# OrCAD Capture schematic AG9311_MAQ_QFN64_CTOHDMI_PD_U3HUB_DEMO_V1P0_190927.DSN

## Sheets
1 P01 Revision History: title: Revision History; rev: 1.0; note: AG9311-MAQ_QFN64_CtoHDMI_PD_U3HUB
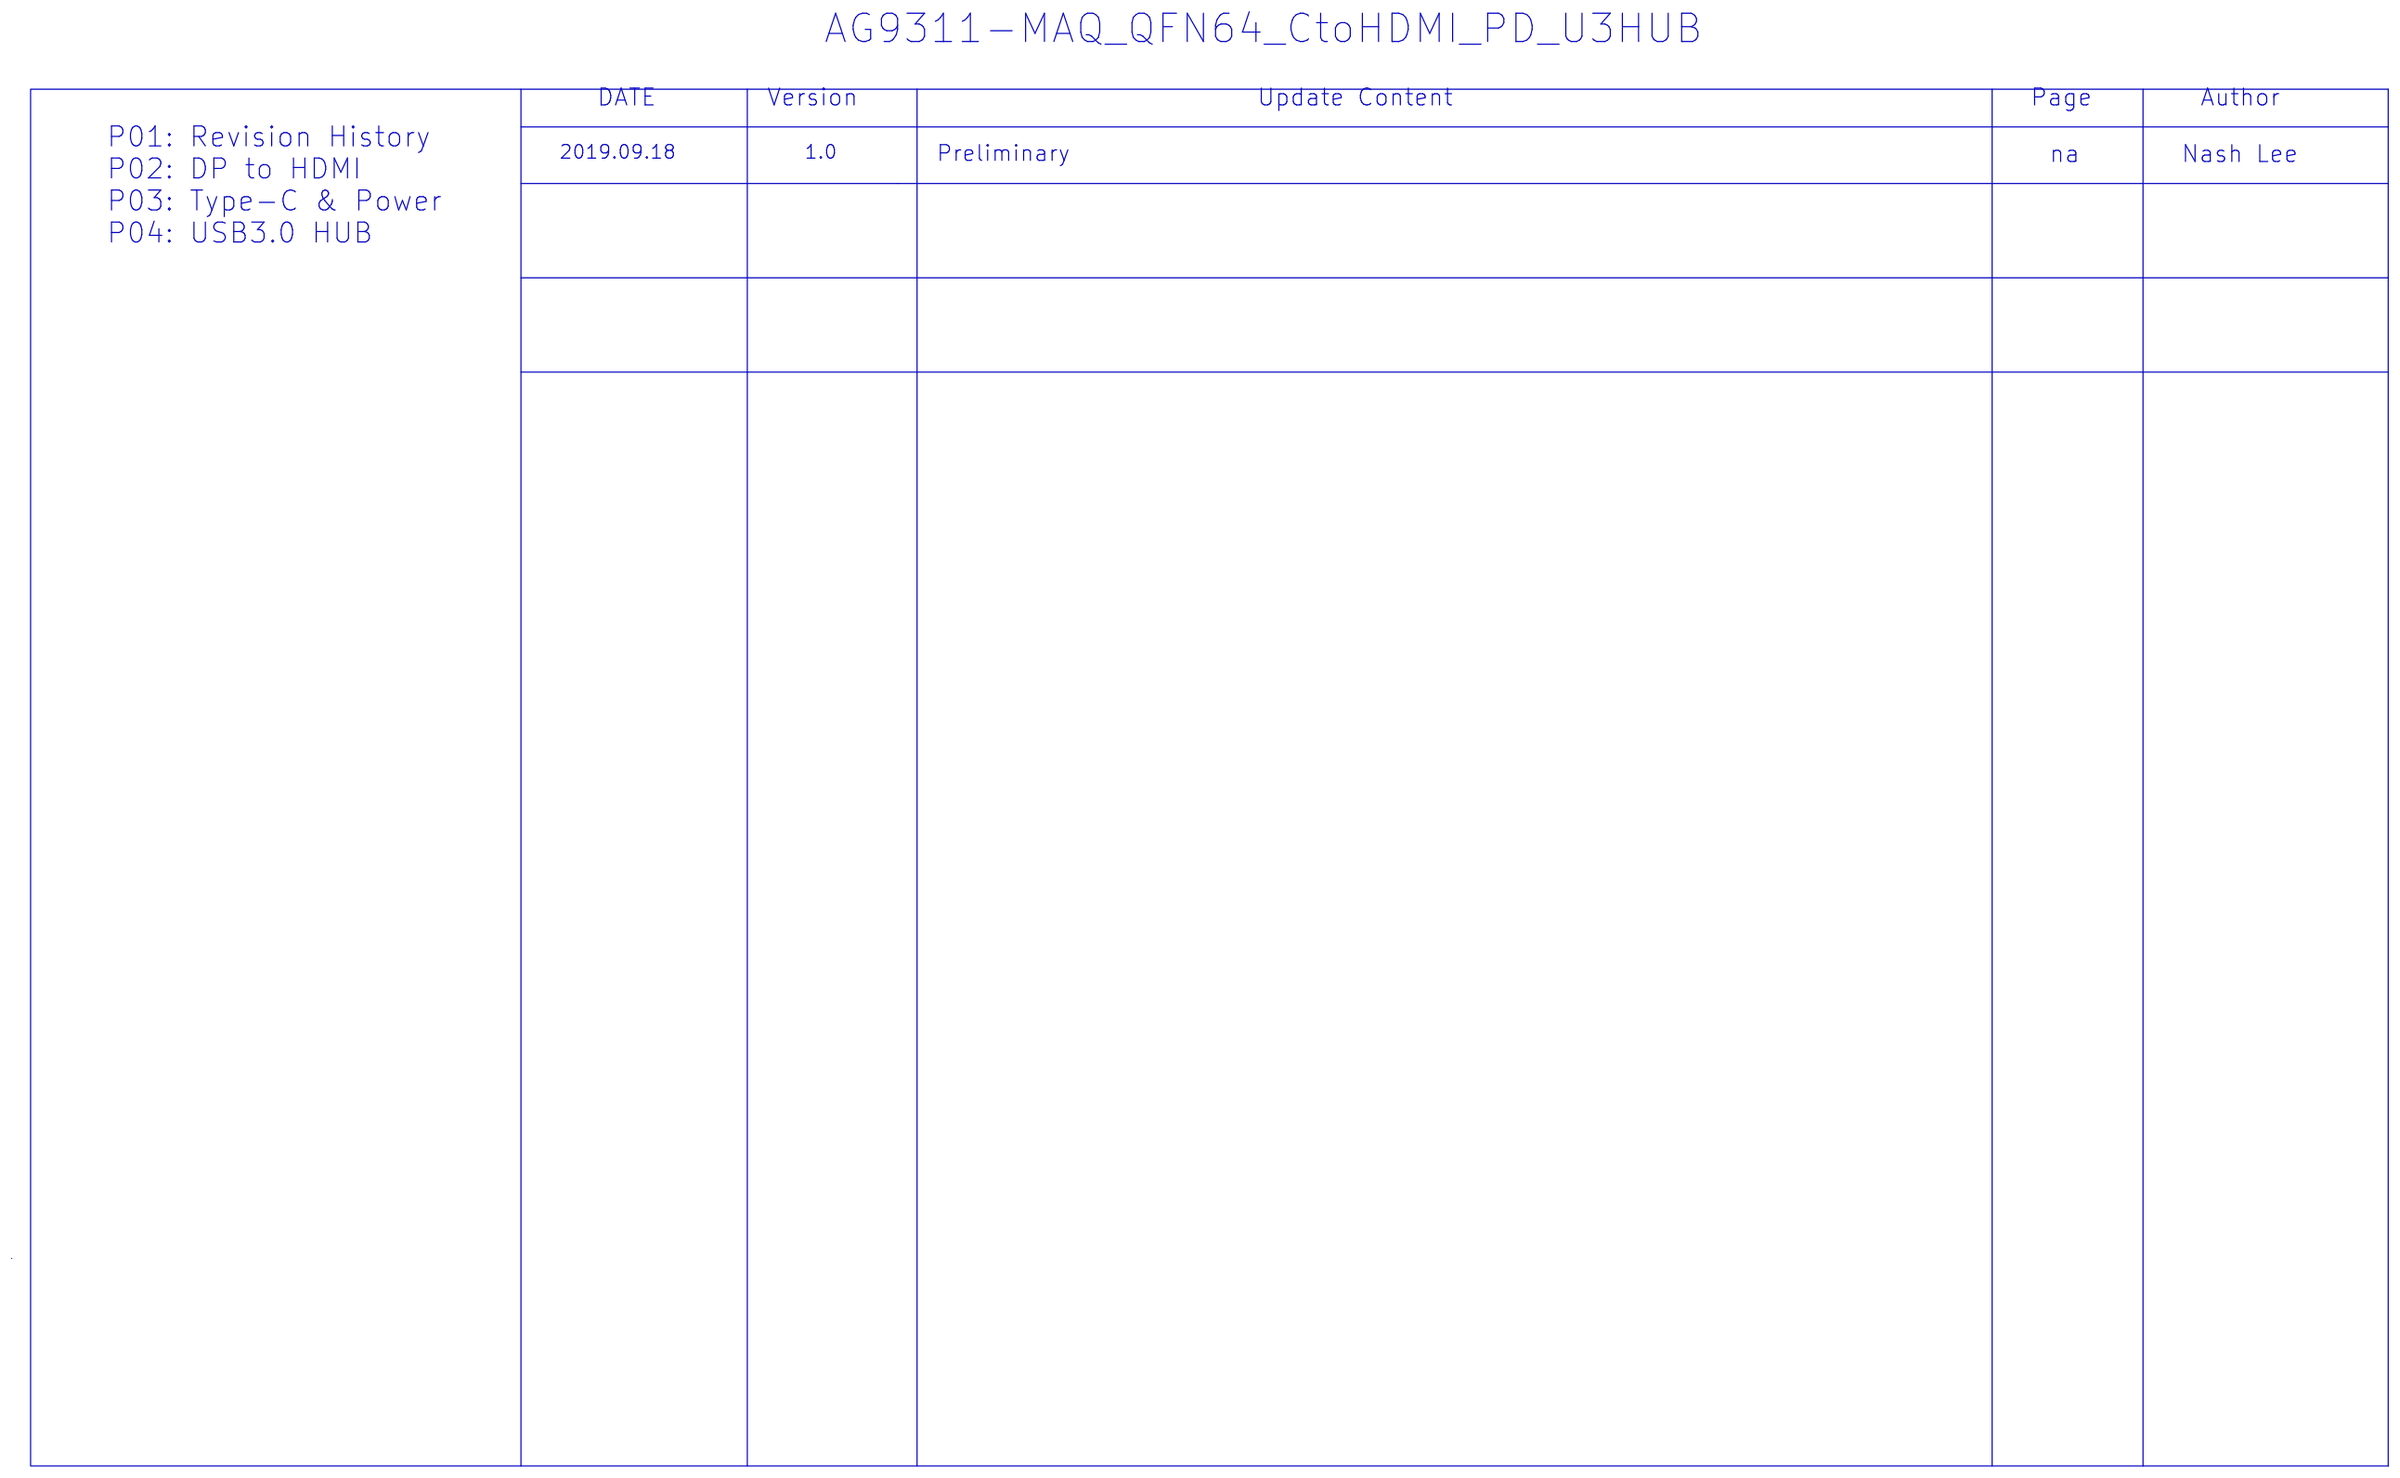
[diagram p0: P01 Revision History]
2 P02 DP to HDMI: size C; title: DP to HDMI
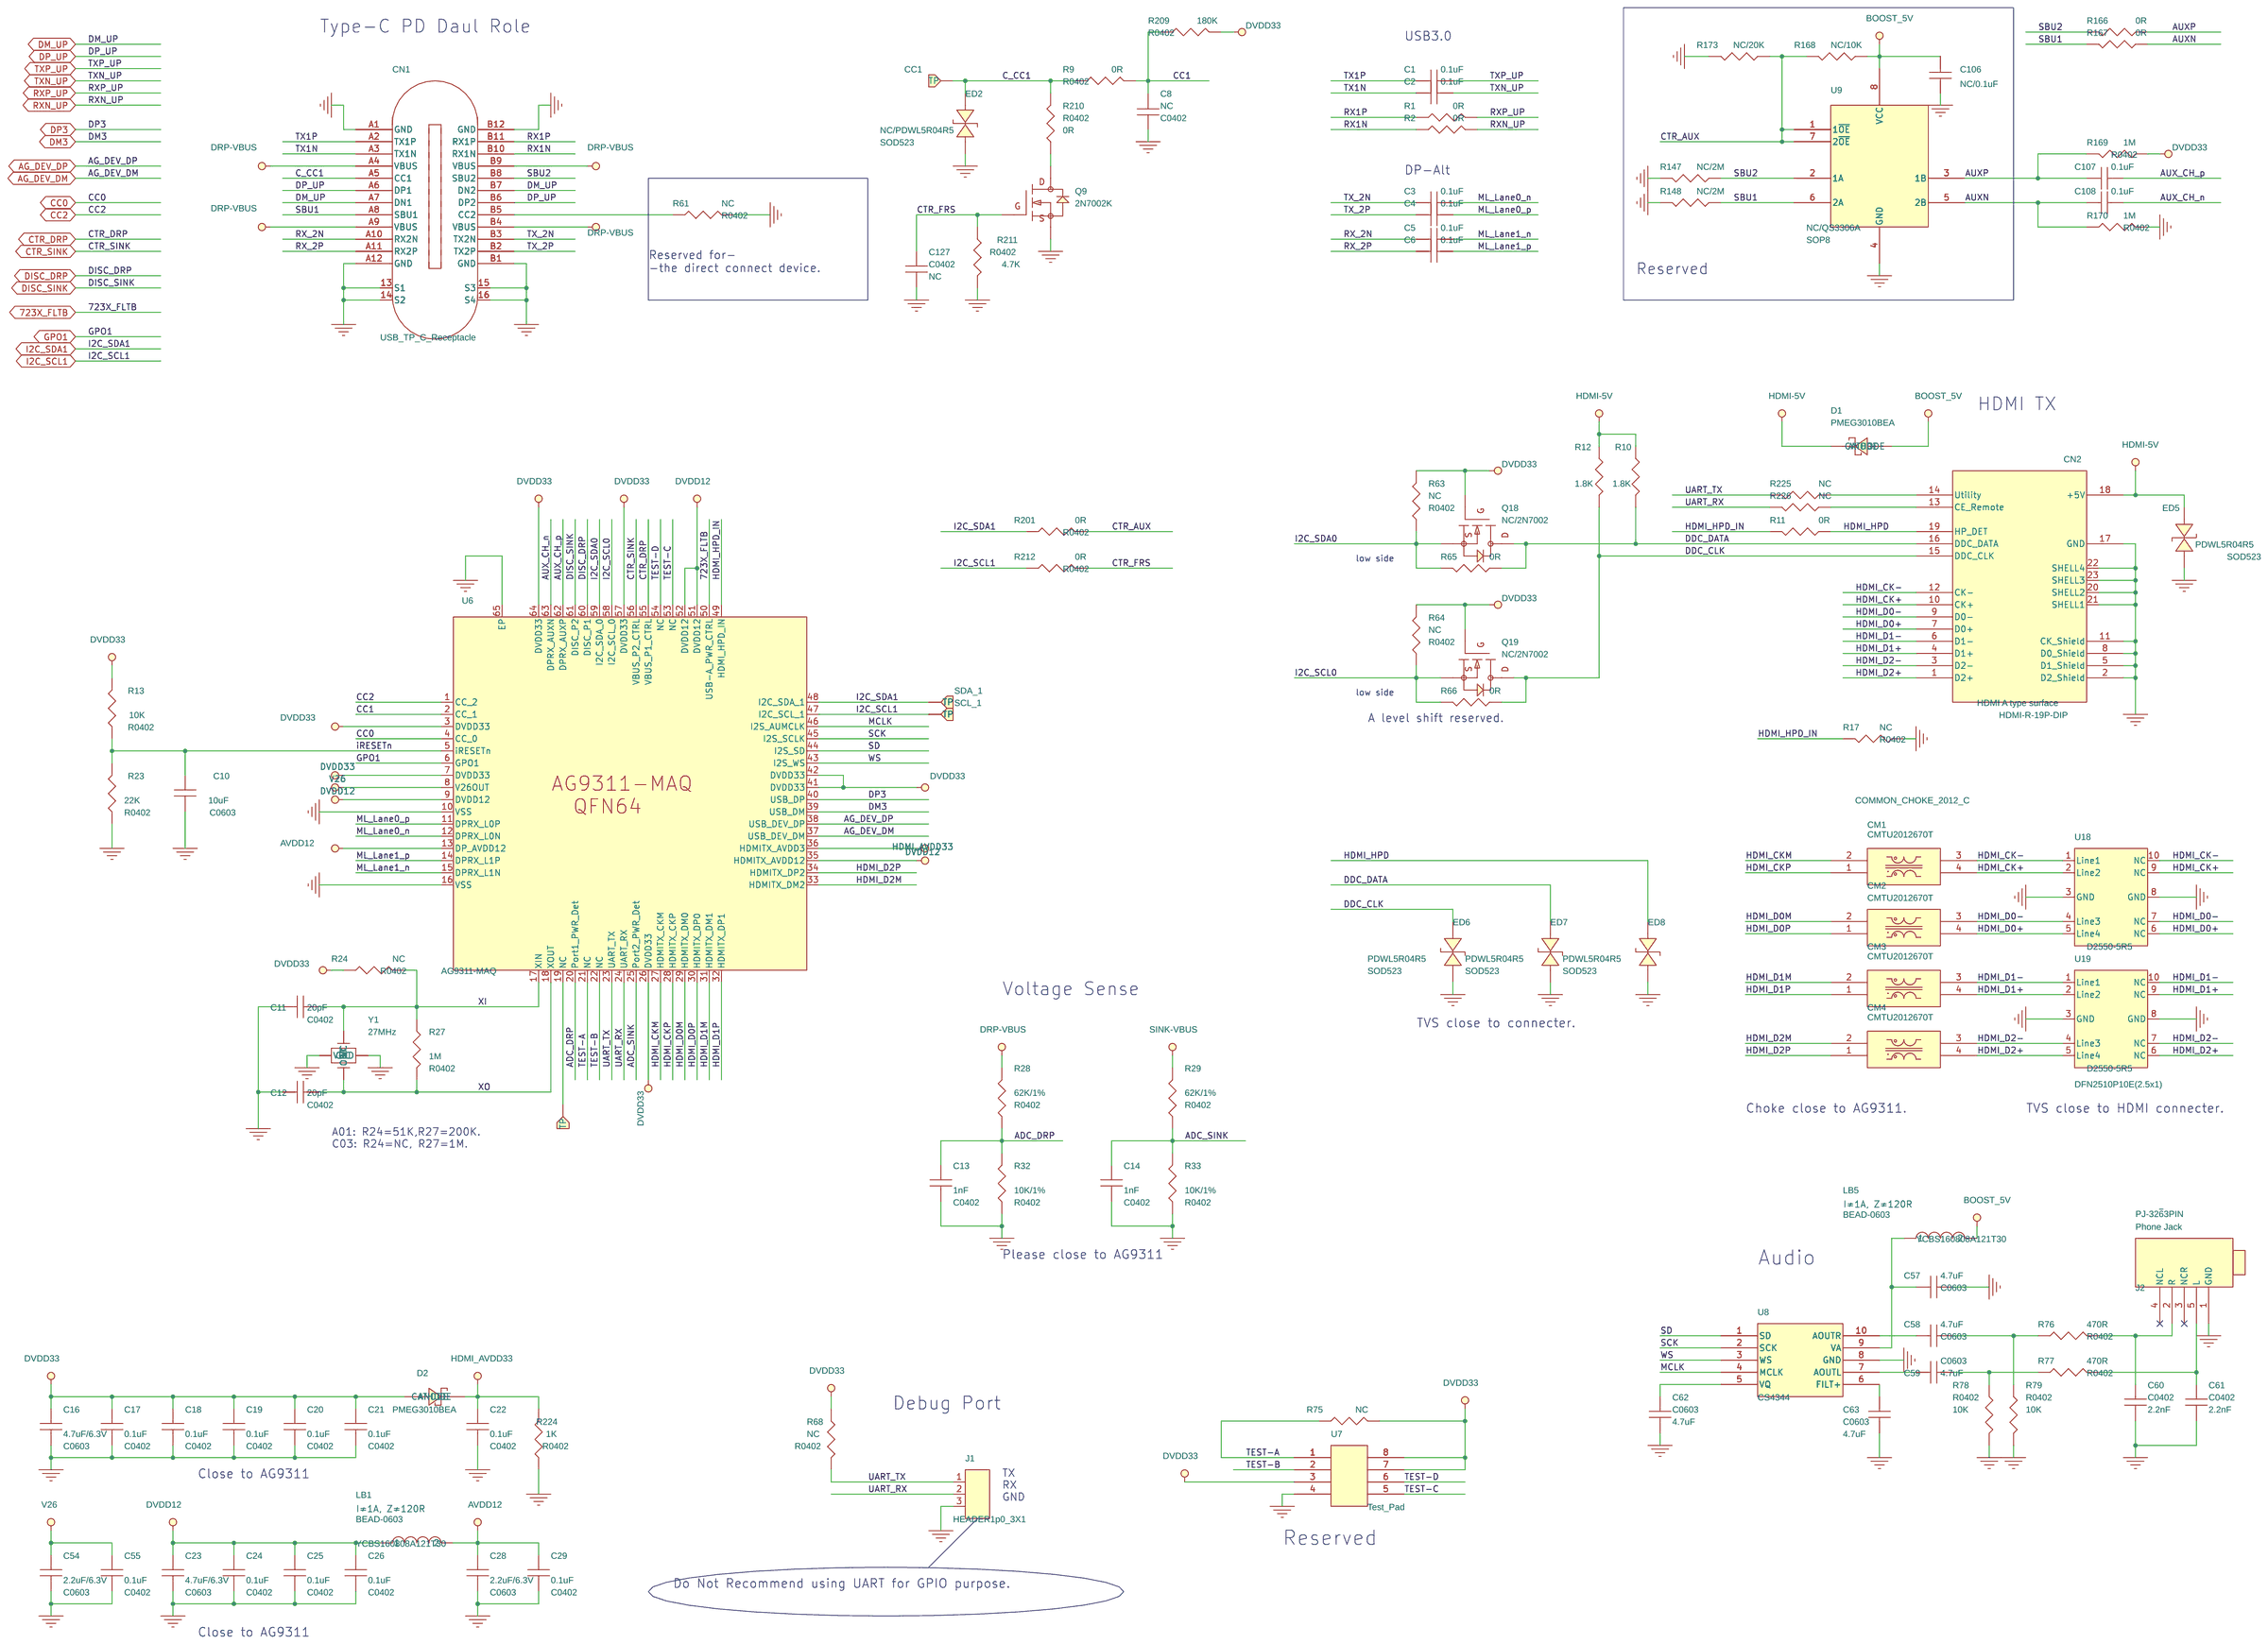
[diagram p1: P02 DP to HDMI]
3 P03 Type-C & Power: size C; title: Type-C & Power
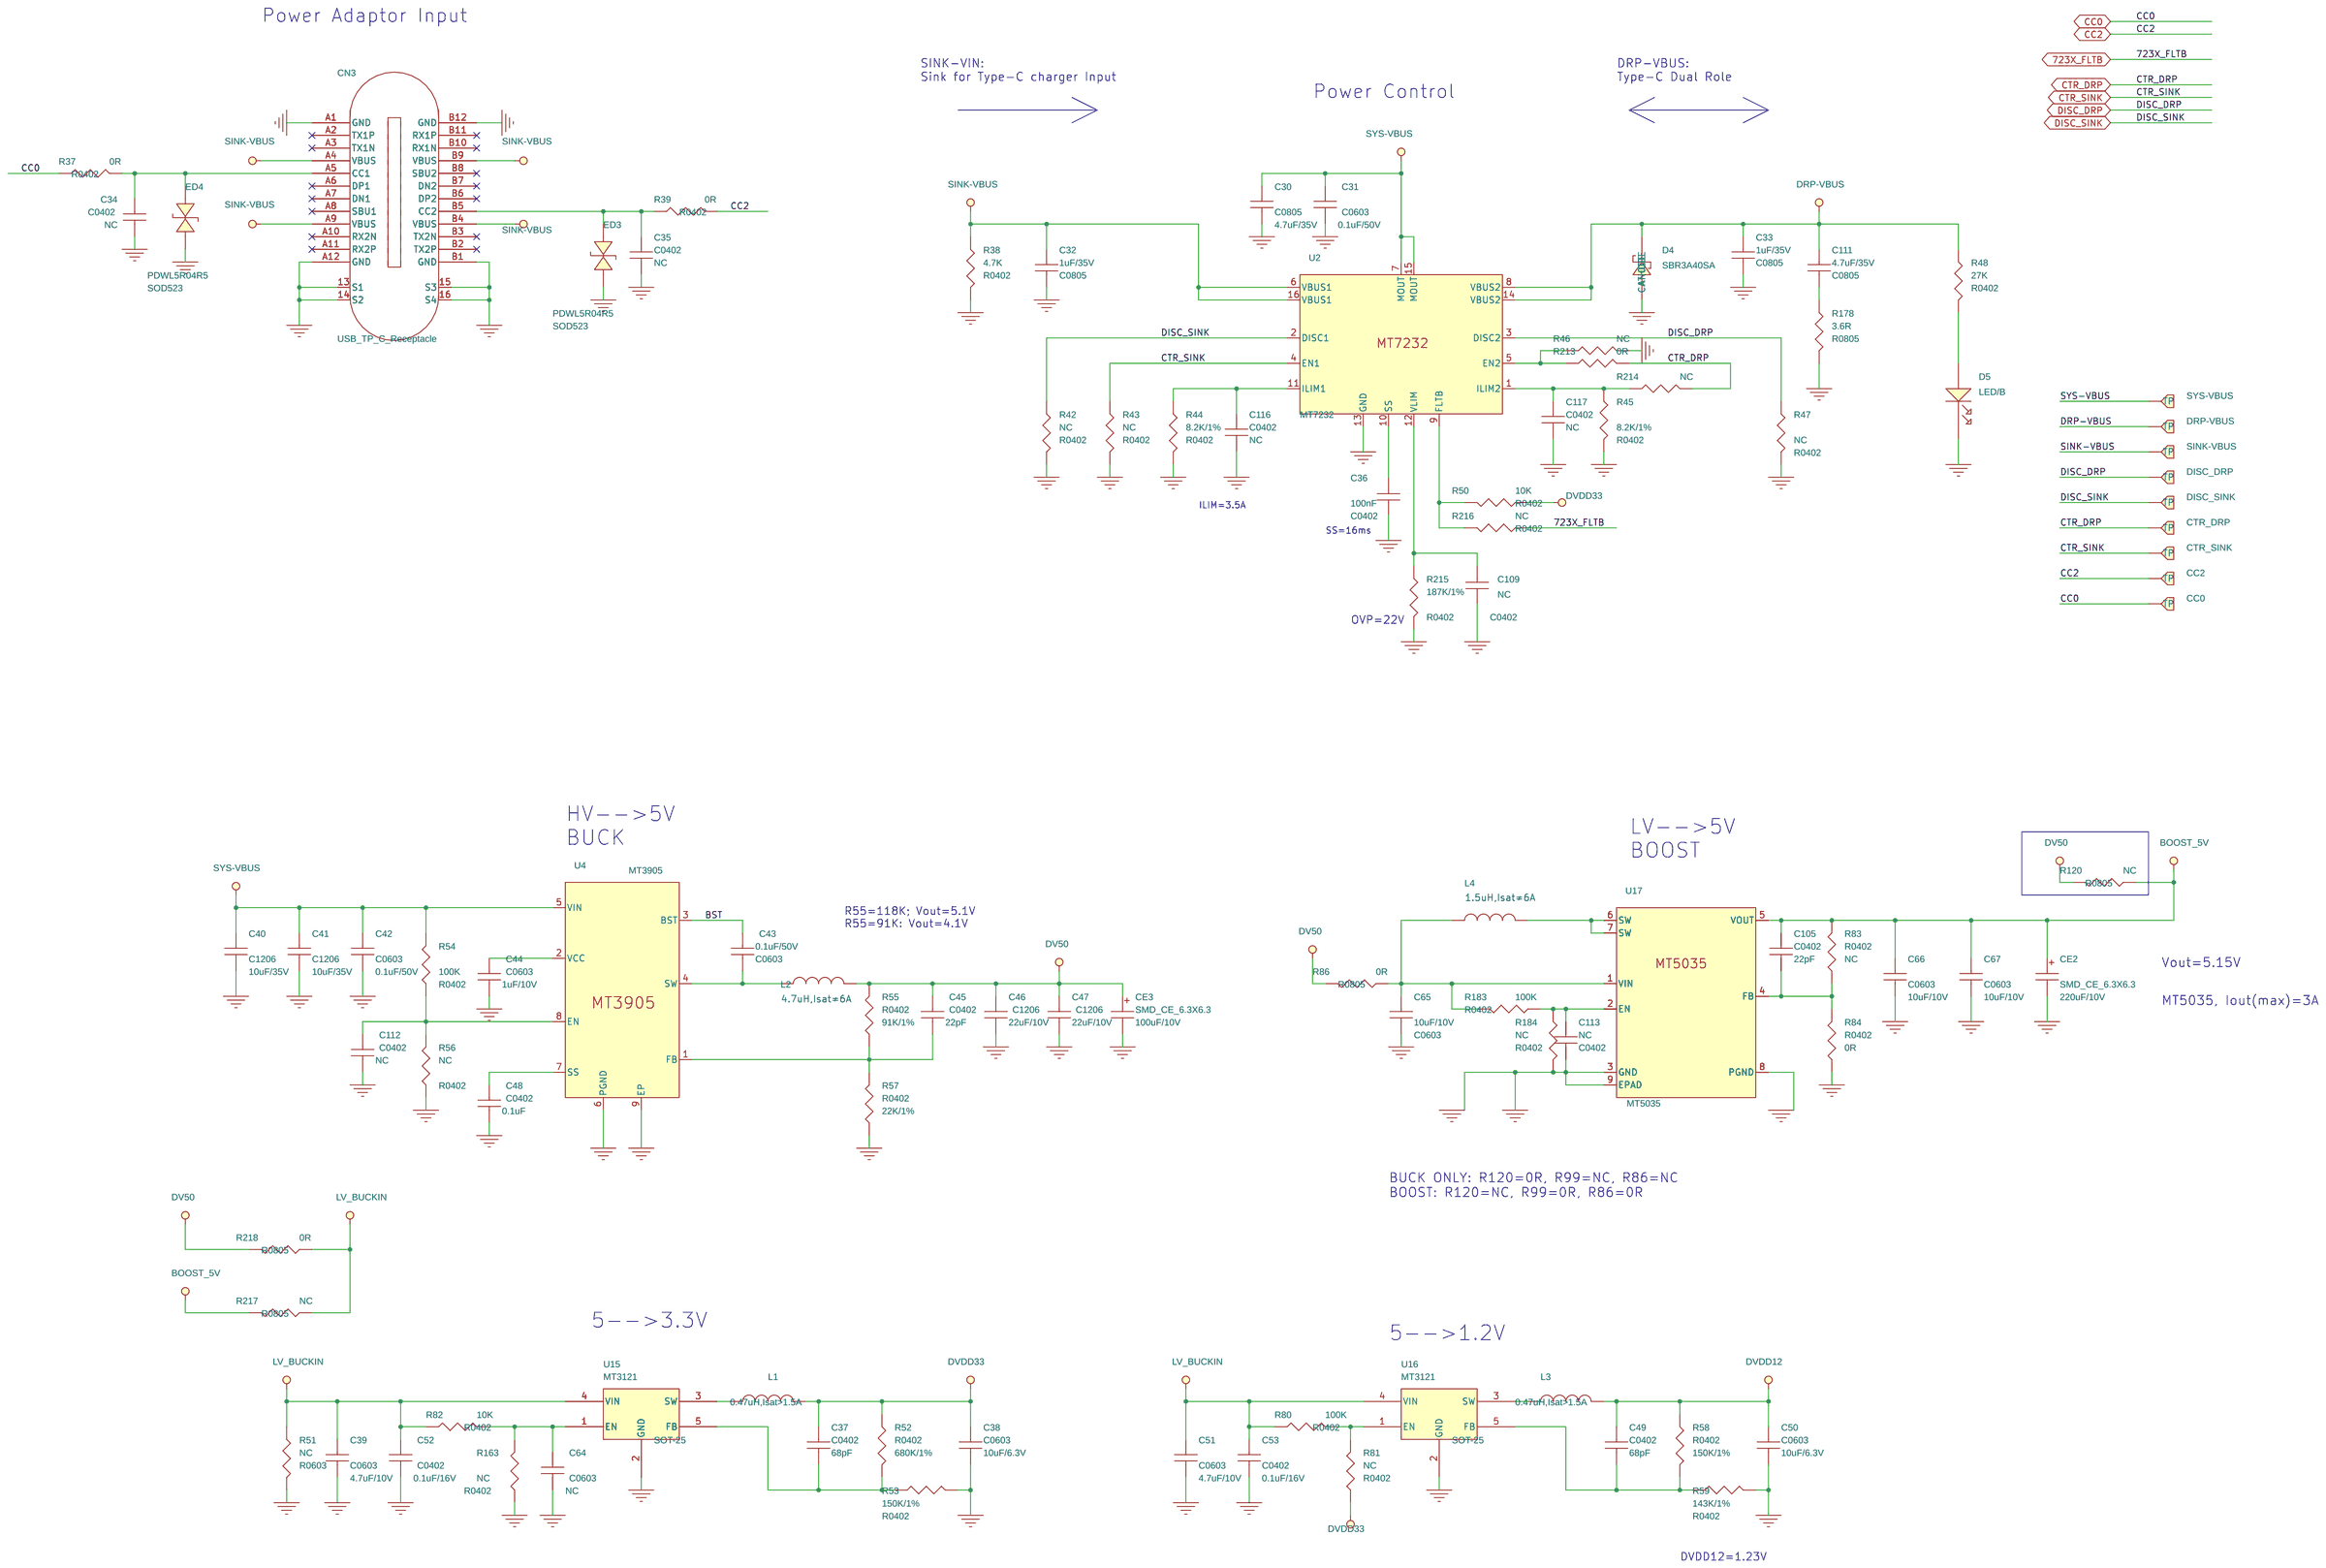
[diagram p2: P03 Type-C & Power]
4 P04 USB3.0 HUB: size C; title: U3HUB
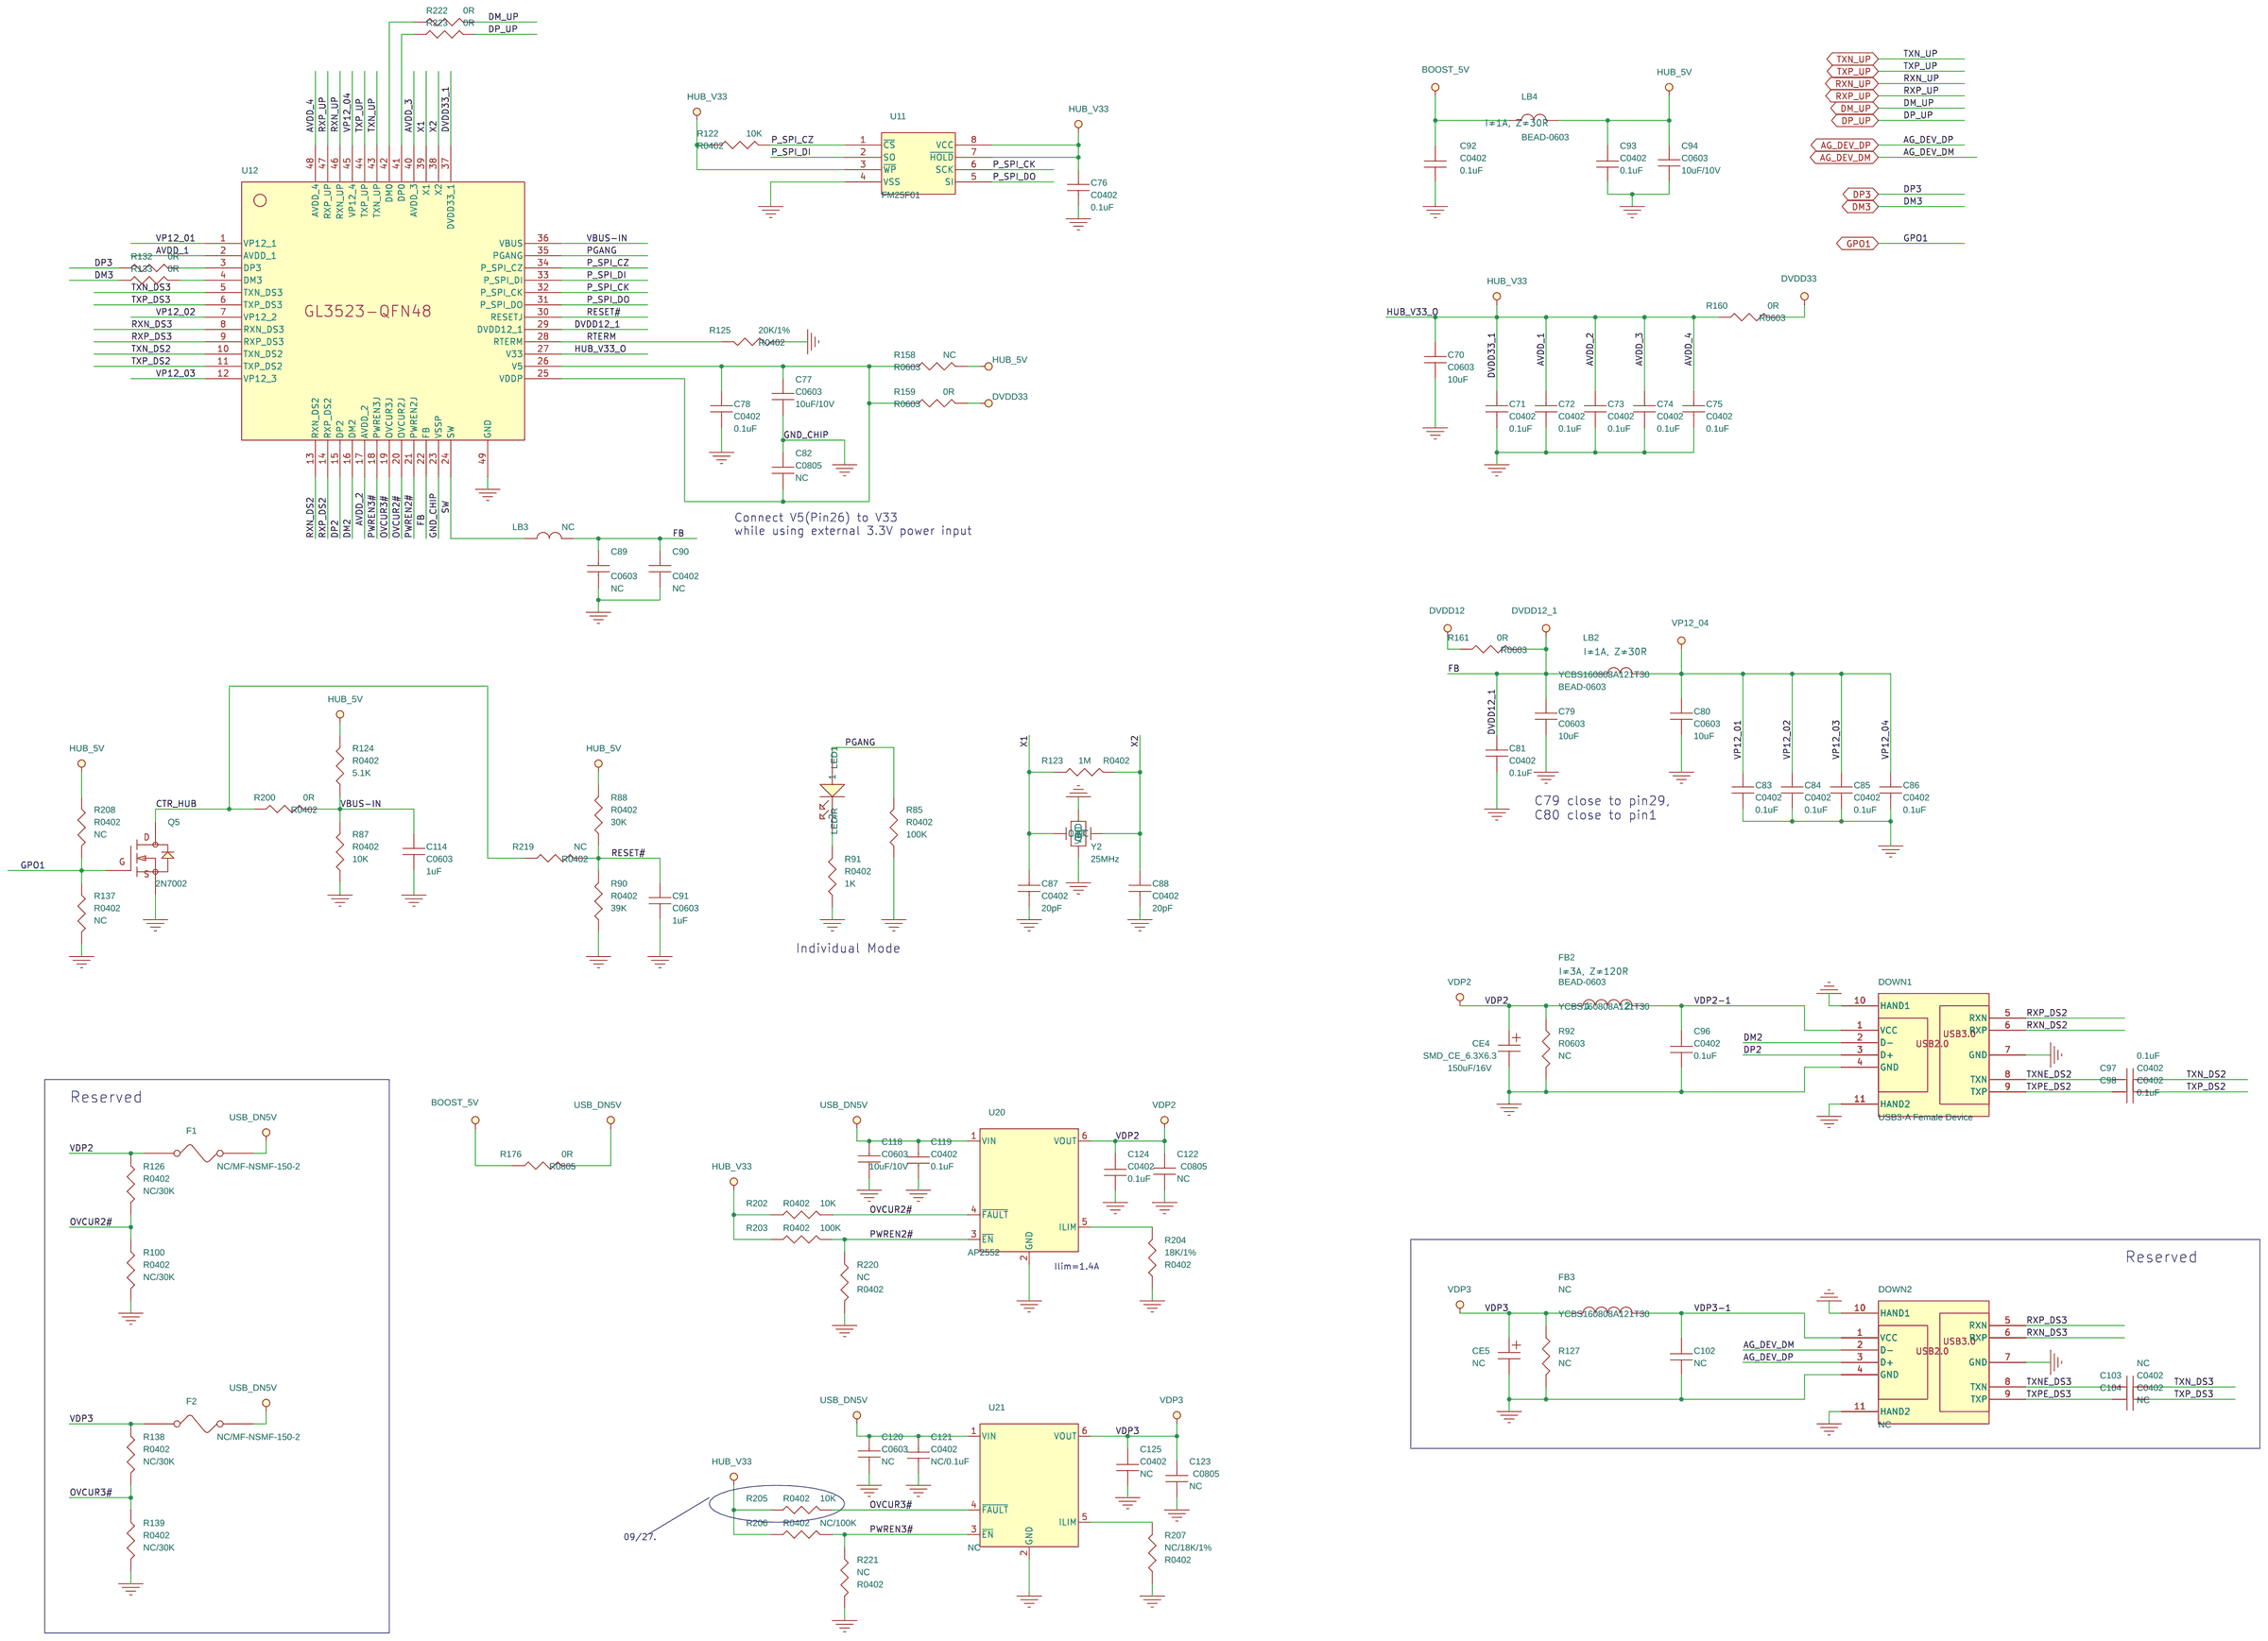
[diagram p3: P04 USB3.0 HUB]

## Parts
sheet P02 DP to HDMI
C1  0.1uF  [C0402]
C2  0.1uF  [C0402]
C3  0.1uF  [C0402]
C4  0.1uF  [C0402]
C5  0.1uF  [C0402]
C6  0.1uF  [C0402]
C8  NC  [C0402]
C10  10uF  [C0603]
C11  20pF  [C0402]
C12  20pF  [C0402]
C13  1nF  [C0402]
C14  1nF  [C0402]
C16  4.7uF/6.3V  [C0603]
C17  0.1uF  [C0402]
C18  0.1uF  [C0402]
C19  0.1uF  [C0402]
C20  0.1uF  [C0402]
C21  0.1uF  [C0402]
C22  0.1uF  [C0402]
C23  4.7uF/6.3V  [C0603]
C24  0.1uF  [C0402]
C25  0.1uF  [C0402]
C26  0.1uF  [C0402]
C28  2.2uF/6.3V  [C0603]
C29  0.1uF  [C0402]
C54  2.2uF/6.3V  [C0603]
C55  0.1uF  [C0402]
C57  4.7uF  [C0603]
C58  4.7uF  [C0603]
C59  4.7uF  [C0603]
C60  2.2nF  [C0402]
C61  2.2nF  [C0402]
C62  4.7uF  [C0603]
C63  4.7uF  [C0603]
C106  NC/0.1uF  [C0402]
C107  0.1uF  [C0402]
C108  0.1uF  [C0402]
C127  NC  [C0402]
CM1  CMTU2012670T  [COMMON_CHOKE_2012_C]
CM2  CMTU2012670T  [COMMON_CHOKE_2012_C]
CM3  CMTU2012670T  [COMMON_CHOKE_2012_C]
CM4  CMTU2012670T  [COMMON_CHOKE_2012_C]
CN1  USB_TP_C_Receptacle  [USB_TYPE_C_FEMALE_DIP_A0353-001]
CN2  HDMI A type surface  [HDMI-R-19P-DIP]
D1  PMEG3010BEA  [SOD323]
D2  PMEG3010BEA  [SOD323]
ED2  NC/PDWL5R04R5  [SOD523]
ED5  PDWL5R04R5  [SOD523]
ED6  PDWL5R04R5  [SOD523]
ED7  PDWL5R04R5  [SOD523]
ED8  PDWL5R04R5  [SOD523]
J1  HEADER1p0_3X1  [HEADER1p0_3X1]
J2  Phone Jack  [PJ-326\3PIN]
LB1  I≠1A, Z≠120R  [BEAD-0603]
LB5  I≠1A, Z≠120R  [BEAD-0603]
Q9  2N7002K  [SOT23-GDS]
Q18  NC/2N7002  [SOT23-GDS]
Q19  NC/2N7002  [SOT23-GDS]
R1  0R  [R0402]
R2  0R  [R0402]
R9  0R  [R0402]
R10  1.8K  [R0402]
R11  0R  [R0402]
R12  1.8K  [R0402]
R13  10K  [R0402]
R17  NC  [R0402]
R23  22K  [R0402]
R24  NC  [R0402]
R27  1M  [R0402]
R28  62K/1%  [R0402]
R29  62K/1%  [R0402]
R32  10K/1%  [R0402]
R33  10K/1%  [R0402]
R61  NC  [R0402]
R63  NC  [R0402]
R64  NC  [R0402]
R65  0R  [R0402]
R66  0R  [R0402]
R68  NC  [R0402]
R75  NC  [R0402]
R76  470R  [R0402]
R77  470R  [R0402]
R78  10K  [R0402]
R79  10K  [R0402]
R147  NC/2M  [R0402]
R148  NC/2M  [R0402]
R166  0R  [R0402]
R167  0R  [R0402]
R168  NC/10K  [R0402]
R169  1M  [R0402]
R170  1M  [R0402]
R173  NC/20K  [R0402]
R201  0R  [R0402]
R209  180K  [R0402]
R210  0R  [R0402]
R211  4.7K  [R0402]
R212  0R  [R0402]
R224  1K  [R0402]
R225  NC  [R0402]
R226  NC  [R0402]
TP1  CC1  [TEST-PAD]
TP12  SYS-VBUS  [TEST-PAD]
TP13  SDA_1  [TEST-PAD]
TP14  SCL_1  [TEST-PAD]
U6  AG9311-MAQ  [QFN64P(8X8)-0.4-EP]
U7  Test_Pad  [SOP8]
U8  CS4344  [TSSOP10]
U9  NC/QS3306A  [SOP8]
U18  D2550-5R5  [DFN2510P10E(2.5x1)]
U19  D2550-5R5  [DFN2510P10E(2.5x1)]
Y1  27MHz  [XTAL3225]
sheet P03 Type-C & Power
C30  4.7uF/35V  [C0805]
C31  0.1uF/50V  [C0603]
C32  1uF/35V  [C0805]
C33  1uF/35V  [C0805]
C34  NC  [C0402]
C35  NC  [C0402]
C36  100nF  [C0402]
C37  68pF  [C0402]
C38  10uF/6.3V  [C0603]
C39  4.7uF/10V  [C0603]
C40  10uF/35V  [C1206]
C41  10uF/35V  [C1206]
C42  0.1uF/50V  [C0603]
C43  0.1uF/50V  [C0603]
C44  1uF/10V  [C0603]
C45  22pF  [C0402]
C46  22uF/10V  [C1206]
C47  22uF/10V  [C1206]
C48  0.1uF  [C0402]
C49  68pF  [C0402]
C50  10uF/6.3V  [C0603]
C51  4.7uF/10V  [C0603]
C52  0.1uF/16V  [C0402]
C53  0.1uF/16V  [C0402]
C64  NC  [C0603]
C65  10uF/10V  [C0603]
C66  10uF/10V  [C0603]
C67  10uF/10V  [C0603]
C105  22pF  [C0402]
C109  NC  [C0402]
C111  4.7uF/35V  [C0805]
C112  NC  [C0402]
C113  NC  [C0402]
C116  NC  [C0402]
C117  NC  [C0402]
CE2  220uF/10V  [SMD_CE_6.3X6.3]
CE3  100uF/10V  [SMD_CE_6.3X6.3]
CN3  USB_TP_C_Receptacle  [USB_TYPE_C_FEMALE_DIP_A0353-001]
D4  SBR3A40SA  [SMA-SBR3A40SA]
D5  LED/B  [LED0603]
ED3  PDWL5R04R5  [SOD523]
ED4  PDWL5R04R5  [SOD523]
L1  0.47uH,Isat>1.5A  [GSDR31]
L2  4.7uH,Isat≠6A  [SMD-L-STMPD0603]
L3  0.47uH,Isat>1.5A  [GSDR31]
L4  1.5uH,Isat≠6A  [SMD-L-STMPD0603]
R37  0R  [R0402]
R38  4.7K  [R0402]
R39  0R  [R0402]
R42  NC  [R0402]
R43  NC  [R0402]
R44  8.2K/1%  [R0402]
R45  8.2K/1%  [R0402]
R46  NC  [R0402]
R47  NC  [R0402]
R48  27K  [R0402]
R50  10K  [R0402]
R51  NC  [R0603]
R52  680K/1%  [R0402]
R53  150K/1%  [R0402]
R54  100K  [R0402]
R55  91K/1%  [R0402]
R56  NC  [R0402]
R57  22K/1%  [R0402]
R58  150K/1%  [R0402]
R59  143K/1%  [R0402]
R80  100K  [R0402]
R81  NC  [R0402]
R82  10K  [R0402]
R83  NC  [R0402]
R84  0R  [R0402]
R86  0R  [R0805]
R120  NC  [R0805]
R163  NC  [R0402]
R178  3.6R  [R0805]
R183  100K  [R0402]
R184  NC  [R0402]
R213  0R  [R0402]
R214  NC  [R0402]
R215  187K/1%  [R0402]
R216  NC  [R0402]
R217  NC  [R0805]
R218  0R  [R0805]
TP3  SYS-VBUS  [TEST-PAD]
TP4  DRP-VBUS  [TEST-PAD]
TP5  SINK-VBUS  [TEST-PAD]
TP6  DISC_DRP  [TEST-PAD]
TP7  DISC_SINK  [TEST-PAD]
TP8  CTR_DRP  [TEST-PAD]
TP9  CTR_SINK  [TEST-PAD]
TP10  CC2  [TEST-PAD]
TP11  CC0  [TEST-PAD]
U2  MT7232  [QFN16P(2.3X3.5)]
U4  MT3905  [SOP8-EP]
U15  MT3121  [SOT-25]
U16  MT3121  [SOT-25]
U17  MT5035  [SOP8-EP]
sheet P04 USB3.0 HUB
C70  10uF  [C0603]
C71  0.1uF  [C0402]
C72  0.1uF  [C0402]
C73  0.1uF  [C0402]
C74  0.1uF  [C0402]
C75  0.1uF  [C0402]
C76  0.1uF  [C0402]
C77  10uF/10V  [C0603]
C78  0.1uF  [C0402]
C79  10uF  [C0603]
C80  10uF  [C0603]
C81  0.1uF  [C0402]
C82  NC  [C0805]
C83  0.1uF  [C0402]
C84  0.1uF  [C0402]
C85  0.1uF  [C0402]
C86  0.1uF  [C0402]
C87  20pF  [C0402]
C88  20pF  [C0402]
C89  NC  [C0603]
C90  NC  [C0402]
C91  1uF  [C0603]
C92  0.1uF  [C0402]
C93  0.1uF  [C0402]
C94  10uF/10V  [C0603]
C96  0.1uF  [C0402]
C97  0.1uF  [C0402]
C98  0.1uF  [C0402]
C102  NC  [C0402]
C103  NC  [C0402]
C104  NC  [C0402]
C114  1uF  [C0603]
C118  10uF/10V  [C0603]
C119  0.1uF  [C0402]
C120  NC  [C0603]
C121  NC/0.1uF  [C0402]
C122  NC  [C0805]
C123  NC  [C0805]
C124  0.1uF  [C0402]
C125  NC  [C0402]
CE4  150uF/16V  [SMD_CE_6.3X6.3]
CE5  NC  [SMD_CE_6.3X6.3]
DOWN1  USB3-A Female Device  [USB3.0-AF-CONN]
DOWN2  NC  [USB3.0-AF-CONN]
F1  NC/MF-NSMF-150-2  [FUSE1206]
F2  NC/MF-NSMF-150-2  [FUSE1206]
FB2  I≠3A, Z≠120R  [BEAD-0603]
FB3  NC  [BEAD-0603]
LB2  I≠1A, Z≠30R  [BEAD-0603]
LB3  NC  [GSDR31]
LB4  I≠1A, Z≠30R  [BEAD-0603]
LED1  LED/R  [LED0603]
Q5  2N7002  [SOT23-GDS]
R85  100K  [R0402]
R87  10K  [R0402]
R88  30K  [R0402]
R90  39K  [R0402]
R91  1K  [R0402]
R92  NC  [R0603]
R100  NC/30K  [R0402]
R122  10K  [R0402]
R123  1M  [R0402]
R124  5.1K  [R0402]
R125  20K/1%  [R0402]
R126  NC/30K  [R0402]
R127  NC  [R0603]
R132  0R  [R0402]
R133  0R  [R0402]
R137  NC  [R0402]
R138  NC/30K  [R0402]
R139  NC/30K  [R0402]
R158  NC  [R0603]
R159  0R  [R0603]
R160  0R  [R0603]
R161  0R  [R0603]
R176  0R  [R0805]
R200  0R  [R0402]
R202  10K  [R0402]
R203  100K  [R0402]
R204  18K/1%  [R0402]
R205  10K  [R0402]
R206  NC/100K  [R0402]
R207  NC/18K/1%  [R0402]
R208  NC  [R0402]
R219  NC  [R0402]
R220  NC  [R0402]
R221  NC  [R0402]
R222  0R  [R0402]
R223  0R  [R0402]
U11  FM25F01  [SOP8]
U12  GL3523_QFN48_V094-1_42  [QFN48P(6X6)-0.4-EP]
U20  AP2552  [SOT-26]
U21  NC  [SOT-26]
Y2  25MHz  [XTAL3225]

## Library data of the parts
C1-C6 C8 = CAP_NP_1
C10-C14 C16 C23 C28 C37-C39 C49-C51 C54 C65-C67 C105 = CAP_0603_5
C17-C22 C24-C26 C29 C55 C92 C93 C96-C98 C102-C104 C107 C108 C119 C121 C124 C125 = CAP_0402_1
C57-C63 = CAP_0603_8
C106 = CAP_0402_0
C127 = CAP_NP_0
CM1-CM4 = CM_TCF03025DH
CN1 CN3 = USB_TP_C_Receptacle
CN2 = HDMI_CNNT_5: P/N: 11.190M4G007; PN0: 11.190M4G002; PN0D: CNNT HDMI M 19P 0.5mm SMT/RT 47151-1101; "MOLEX
D1 = DIODE_SCHOTTKY_2: Location: T; P/N: 09.PMEG4G001
D2 = DIODE_SCHOTTKY_3: Location: T; P/N: 09.PMEG4G001
ED2-ED8 = ESD_0: Layer: BOT; P/N: 09.PESD5GV0B
J1 = HEADER254_3X1
J2 = 74AUP1T45_1
FB2 LB1 = INDUCTOR: P/N: YCBS160808A121T30
LB5 = INDUCTOR_1: P/N: YCBS160808A121T30
Q9 = AO3418
Q5 Q18 Q19 = 2N7002_0
R1 R2 = R-0402
R9 R209-R211 = R_0
R10-R13 R17 R23 R24 R27-R29 R32 R33 R38 R42 R43 R45-R48 R52 R53 R58 R59 R65 R66 R68 R76-R79 R147 R148 R166-R170 R173 R178 R200 R201 R212-R214 R219 R224-R226 = R-0603_12
R61 = R-0603_9
R54-R57 R63 R64 R83 R84 R86 R120 R183 R184 R217 R218 = R-0603_7
R51 R75 R80-R82 R163 = R_6
TP1 TP3-TP14 = T_POINT_F
U6 = AG9311-MAQ-QFN64_2
U7 = FM25F005_SOP8_1
U8 = 100201_SO_5
U9 = 24C16_7: Layer: TOP; P/N: PCA9306DCUR
U18 U19 = AZ1023-04F
Y1 Y2 = CRYSTAL_SMD
C30 C32 C33 C40 C41 C46 C47 C111 C122 C123 = CAP_1206
C31 C34 C35 C42-C45 C48 C52 C53 C64 C70-C76 C78-C81 C83-C91 C94 C112-C114 C116-C118 C120 = CAP_0603
C36 C109 = CAP_0805_0
CE2 CE3 = ECAP_D_0
D4 = DIODE_SCHOTTKY_5: Location: T; P/N: 09.PMEG4G001
D5 = LED_5
L1 L3 = INDUCTOR_5
L2 L4 = INDUCTOR_6
R37 R39 R44 R50 R215 R216 = R-0603_14
U2 = MT7232
U4 = MT3905
U15 U16 = MIC29302_0
U17 = MT5033_0
C77 C82 = CAP_0805
CE4 CE5 = CAP_SMD
DOWN1 DOWN2 = USB3-A_0
F1 F2 = FS-A
FB3 = FB1608: P/N: YCBS160808A121T30
LB2 = GBD201209PGH501N: P/N: YCBS160808A121T30
LB3 = FB-0805
LB4 = GBD201209PGH501N
LED1 = LED-0805_2
R85 R87 R88 R90-R92 R100 R122-R127 R132 R133 R138 R139 R158-R161 R176 R202-R207 R220-R223 = R-0603
R137 R208 = R_7
U11 = CAT25C128_256
U12 = GL3523_QFN48_V094-1_0
U20 U21 = AP2552

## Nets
AVDD12: C28.1 C29.1 LB1.2 U6.13(DP_AVDD12)
DV50: C45.1 C46.1 C47.1 CE3.1 L2.2 R55.2 R86.2 R120.2 R218.2
DVDD12: C23.1 C24.1 C25.1 C26.1 C49.1 C50.1 L3.2 LB1.1 R58.1 R161.2 U6.9(DVDD12) U6.35(HDMITX_AVDD12) U6.51(DVDD12) U6.52(DVDD12)
DVDD33: C16.1 C17.1 C18.1 C19.1 C20.1 C21.1 C37.1 C38.1 D2.A(ANODE) L1.2 Q18.G(GATE) Q19.G(GATE) R13.1 R24.1 R50.2 R52.1 R63.1 R64.1 R68.2 R75.1 R81.1 R159.2 R160.1 R169.1 R209.2 U6.3(DVDD33) U6.7(DVDD33) U6.26(DVDD33) U6.41(DVDD33) U6.42(DVDD33) U6.57(DVDD33) U6.64(DVDD33) U7.3 U7.7 U7.8
GND: C8.1 C10.2 C11.1 C12.1 C13.2 C14.2 C16.2 C17.2 C18.2 C19.2 C20.2 C21.2 C22.2 C23.2 C24.2 C25.2 C26.2 C28.2 C29.2 C30.2 C31.2 C32.2 C33.2 C34.2 C35.2 C36.1 C38.2 C39.2 C40.2 C41.2 C42.2 C44.2 C46.2 C47.2 C48.2 C50.2 C51.2 C52.2 C53.2 C54.2 C55.2 C57.2 C60.2 C61.2 C62.2 C63.2 C64.2 C65.2 C66.2 C67.2 C70.2 C71.2 C72.2 C73.2 C74.2 C75.2 C76.2 C77.2 C78.2 C79.2 C80.2 C81.2 C82.1 C83.2 C84.2 C85.2 C86.2 C87.2 C88.2 C89.2 C90.2 C91.2 C92.1 C93.1 C94.2 C96.1 C102.1 C106.1 C109.1 C112.2 C113.2 C114.2 C116.2 C117.2 C118.2 C119.1 C120.2 C121.1 C122.2 C123.2 C124.1 C125.1 C127.2 CE2.2 CE3.2 CE4.2 CE5.2 CN1.13(S1) CN1.14(S2) CN1.15(S3) CN1.16(S4) CN1.A1(GND) CN1.A12(GND) CN1.B1(GND) CN1.B12(GND) CN2.2(D2_Shield) CN2.5(D1_Shield) CN2.8(D0_Shield) CN2.11(CK_Shield) CN2.17(GND) CN2.20(SHELL2) CN2.21(SHELL1) CN2.22(SHELL4) CN2.23(SHELL3) CN3.13(S1) CN3.14(S2) CN3.15(S3) CN3.16(S4) CN3.A1(GND) CN3.A12(GND) CN3.B1(GND) CN3.B12(GND) D4.A(ANODE) D5.K(CATHODE) DOWN1.4(GND) DOWN1.7(GND) DOWN1.10(HAND1) DOWN1.11(HAND2) DOWN2.4(GND) DOWN2.7(GND) DOWN2.10(HAND1) DOWN2.11(HAND2) ED2.2 ED3.2 ED4.2 ED5.2 ED6.2 ED7.2 ED8.2 J1.3 J2.1(GND) Q5.S(SOURCE) Q9.S(SOURCE) R17.1 R23.2 R32.1 R33.1 R38.2 R42.2 R43.2 R44.2 R45.2 R46.2 R47.2 R51.2 R53.2 R56.1 R57.1 R59.2 R61.2 R78.2 R79.2 R84.1 R85.1 R87.1 R90.1 R91.1 R92.2 R100.2 R125.1 R127.2 R137.2 R139.2 R147.2 R148.2 R163.1 R170.2 R173.1 R178.2 R184.2 R204.1 R207.1 R211.2 R215.1 R220.2 R221.2 R224.1 U2.13(GND) U4.6(PGND) U4.9(EP) U6.10(VSS) U6.16(VSS) U6.65(EP) U7.4 U8.8(GND) U9.4(GND) U11.4(VSS) U12.23(VSSP) U12.49(GND) U15.2(GND) U16.2(GND) U17.3(GND) U17.8(PGND) U17.9(EPAD) U18.3(GND) U18.8(GND) U19.3(GND) U19.8(GND) U20.2(GND) U21.2(GND) Y1.2(GND) Y1.4(VDC) Y2.2(GND) Y2.4(VDC)
V26: C54.1 C55.1 U6.8(V26OUT)
VBUS-IN: C114.1 R87.2 R124.1 R200.1 U12.36(VBUS)
723X_FLTB: R216.2 U6.50(USB-A_PWR_CTRL)
ADC_DRP: C13.1 R28.1 R32.2 U6.20(Port1_PWR_Det)
ADC_SINK: C14.1 R29.1 R33.2 U6.25(Port2_PWR_Det)
AG_DEV_DM: DOWN2.2(D-) U6.37(USB_DEV_DM)
AG_DEV_DP: DOWN2.3(D+) U6.38(USB_DEV_DP)
AUX_CH_n: C108.2 U6.63(DPRX_AUXN)
AUX_CH_p: C107.2 U6.62(DPRX_AUXP)
AUXN: C108.1 R167.1 R170.1 U9.5(2B)
AUXP: C107.1 R166.1 R169.2 U9.3(1B)
BOOST_5V: C66.1 C67.1 C92.2 C105.1 C106.2 CE2.1 D1.A(ANODE) LB4.1 LB5.2 R83.2 R120.1 R168.2 R176.1 R217.2 U9.8(VCC) U17.5(VOUT)
BST: C43.1 U4.3(BST)
C_CC1: CN1.A5(CC1) ED2.1 R9.1 R210.2 TP1.1(TP)
CC0: R37.1 TP11.1(TP) U6.4(CC_0)
CC1: C8.2 R9.2 R209.1 U6.2(CC_1)
CC2: R39.2 TP10.1(TP) U6.1(CC_2)
CTR_AUX: R168.1 R173.2 R201.1 U9.1(1~{OE}) U9.7(2~{OE})
CTR_DRP: R213.2 R214.2 TP8.1(TP) U6.55(VBUS_P1_CTRL)
CTR_FRS: C127.1 Q9.G(GATE) R211.1 R212.1
CTR_HUB: Q5.D(DRAIN) R200.2 R219.2
CTR_SINK: R43.1 TP9.1(TP) U2.4(EN1) U6.56(VBUS_P2_CTRL)
DDC_CLK: CN2.15(DDC_CLK) ED6.1 Q19.D(DRAIN) R12.1 R66.2
DDC_DATA: CN2.16(DDC_DATA) ED7.1 Q18.D(DRAIN) R10.1 R65.2
DISC_DRP: R47.1 TP6.1(TP) U2.3(DISC2) U6.60(DISC_P1)
DISC_SINK: R42.1 TP7.1(TP) U2.2(DISC1) U6.61(DISC_P2)
DM2: DOWN1.2(D-) U12.16(DM2)
DM3: R133.1 U6.39(USB_DM)
DM_UP: CN1.A7(DN1) CN1.B7(DN2) R222.2
DP2: DOWN1.3(D+) U12.15(DP2)
DP3: R132.1 U6.40(USB_DP)
DP_UP: CN1.A6(DP1) CN1.B6(DP2) R223.2
DRP-VBUS: C33.1 C111.1 CN1.A4(VBUS) CN1.A9(VBUS) CN1.B4(VBUS) CN1.B9(VBUS) D4.K(CATHODE) R28.2 R48.1 TP4.1(TP) U2.8(VBUS2) U2.14(VBUS2)
GPO1: Q5.G(GATE) R137.1 R208.2 U6.6(GPO1)
HDMI-5V: CN2.18(+5V) D1.K(CATHODE) ED5.1 R10.2 R12.2
HDMI_AVDD33: C22.1 D2.K(CATHODE) R224.2 U6.36(HDMITX_AVDD3)
HDMI_CK+: CM1.4 CN2.10(CK+) U18.2(Line2) U18.9(NC)
HDMI_CK-: CM1.3 CN2.12(CK-) U18.1(Line1) U18.10(NC)
HDMI_CKM: CM1.2 U6.27(HDMITX_CKM)
HDMI_CKP: CM1.1 U6.28(HDMITX_CKP)
HDMI_D0+: CM2.4 CN2.7(D0+) U18.5(Line4) U18.6(NC)
HDMI_D0-: CM2.3 CN2.9(D0-) U18.4(Line3) U18.7(NC)
HDMI_D0M: CM2.2 U6.29(HDMITX_DM0)
HDMI_D0P: CM2.1 U6.30(HDMITX_DP0)
HDMI_D1+: CM3.4 CN2.4(D1+) U19.2(Line2) U19.9(NC)
HDMI_D1-: CM3.3 CN2.6(D1-) U19.1(Line1) U19.10(NC)
HDMI_D1M: CM3.2 U6.31(HDMITX_DM1)
HDMI_D1P: CM3.1 U6.32(HDMITX_DP1)
HDMI_D2+: CM4.4 CN2.1(D2+) U19.5(Line4) U19.6(NC)
HDMI_D2-: CM4.3 CN2.3(D2-) U19.4(Line3) U19.7(NC)
HDMI_D2M: CM4.2 U6.33(HDMITX_DM2)
HDMI_D2P: CM4.1 U6.34(HDMITX_DP2)
HDMI_HPD: CN2.19(HP_DET) ED8.1 R11.2
HDMI_HPD_IN: R11.1 R17.2 U6.49(HDMI_HPD_IN)
HUB_5V: C93.2 C94.1 LB4.2 R88.2 R124.2 R158.2 R208.1
HUB_AV12: C80.1 C83.1 C84.1 C85.1 C86.1 LB2.2 U12.1(VP12) U12.7(VP12_2) U12.12(VP12_3) U12.45(VP12_4)
HUB_DV12: C79.1 C81.1 C89.1 C90.1 LB2.1 LB3.2 R161.1 U12.22(FB) U12.29(DVDD12_1)
HUB_V33: C70.1 C71.1 C72.1 C73.1 C74.1 C75.1 C76.1 R122.1 R160.2 R202.1 R203.1 R205.1 R206.1 U11.3(~{WP}) U11.7(~{HOLD}) U11.8(VCC) U12.2(AVDD_1) U12.17(AVDD_2) U12.27(V33) U12.37(DVDD33_1) U12.40(AVDD_3) U12.48(AVDD_4)
I2C_SCL0: Q19.S(SOURCE) R64.2 R66.1 U6.58(I2C_SCL_0)
I2C_SCL1: R212.2 TP14.1(TP) U6.47(I2C_SCL_1)
I2C_SDA0: Q18.S(SOURCE) R63.2 R65.1 U6.59(I2C_SDA_0)
I2C_SDA1: R201.2 TP13.1(TP) U6.48(I2C_SDA_1)
iRESETn: C10.1 R13.2 R23.1 U6.5(iRESETn)
LV_BUCKIN: C39.1 C51.1 C52.1 C53.1 R51.1 R80.1 R82.1 R217.1 R218.1 U15.4(VIN) U16.4(VIN)
MCLK: U6.46(I2S_AUMCLK) U8.4(MCLK)
ML_Lane0_n: C3.2 U6.12(DPRX_L0N)
ML_Lane0_p: C4.2 U6.11(DPRX_L0P)
ML_Lane1_n: C5.2 U6.15(DPRX_L1N)
ML_Lane1_p: C6.2 U6.14(DPRX_L1P)
OVCUR2#: R100.1 R126.2 R202.2 U12.20(OVCUR2J) U20.4(~{FAULT})
OVCUR3#: R138.2 R139.1 R205.2 U12.19(OVCUR3J) U21.4(~{FAULT})
P_SPI_CK: U11.6(SCK) U12.32(P_SPI_CK)
P_SPI_CZ: R122.2 U11.1(~{CS}) U12.34(P_SPI_CZ)
P_SPI_DI: U11.2(SO) U12.33(P_SPI_DI)
P_SPI_DO: U11.5(SI) U12.31(P_SPI_DO)
PGANG: LED1.A(1) R85.2 U12.35(PGANG)
PWREN2#: R203.2 R220.1 U12.21(PWREN2J) U20.3(~{EN})
PWREN3#: R206.2 R221.1 U12.18(PWREN3J) U21.3(~{EN})
RESET#: C91.1 R88.1 R90.2 R219.1 U12.30(RESETJ)
RTERM: R125.2 U12.28(RTERM)
RX1N: CN1.B10(RX1N) R2.1
RX1P: CN1.B11(RX1P) R1.1
RX_2N: C5.1 CN1.A10(RX2N)
RX_2P: C6.1 CN1.A11(RX2P)
RXN_DS2: DOWN1.6(RXP) U12.13(RXN_DS2)
RXN_DS3: DOWN2.6(RXP) U12.8(RXN_DS3)
RXN_UP: R2.2 U12.46(RXN_UP)
RXP_DS2: DOWN1.5(RXN) U12.14(RXP_DS2)
RXP_DS3: DOWN2.5(RXN) U12.9(RXP_DS3)
RXP_UP: R1.2 U12.47(RXP_UP)
SBU1: CN1.A8(SBU1) R148.1 R167.2 U9.6(2A)
SBU2: CN1.B8(SBU2) R147.1 R166.2 U9.2(1A)
SCK: U6.45(I2S_SCLK) U8.2(SCK)
SD: U6.44(I2S_SD) U8.1(SD)
SINK-VBUS: C32.1 CN3.A4(VBUS) CN3.A9(VBUS) CN3.B4(VBUS) CN3.B9(VBUS) R29.2 R38.1 TP5.1(TP) U2.6(VBUS1) U2.16(VBUS1)
SW: LB3.1 U12.24(SW)
SYS-VBUS: C30.1 C31.1 C40.1 C41.1 C42.1 R54.2 TP3.1(TP) U2.7(MOUT) U2.15(MOUT) U4.5(VIN)
TEST-A: R75.2 U6.21(NC) U7.1
TEST-B: U6.22(NC) U7.2
TEST-C: U6.53(NC) U7.5
TEST-D: U6.54(NC) U7.6
TX1N: C2.1 CN1.A3(TX1N)
TX1P: C1.1 CN1.A2(TX1P)
TX_2N: C3.1 CN1.B3(TX2N)
TX_2P: C4.1 CN1.B2(TX2P)
TXN_DS2: C97.2 U12.10(TXN_DS2)
TXN_DS3: C103.2 U12.5(TXN_DS3)
TXN_UP: C2.2 U12.43(TXN_UP)
TXNE_DS2: C97.1 DOWN1.8(TXN)
TXNE_DS3: C103.1 DOWN2.8(TXN)
TXP_DS2: C98.2 U12.11(TXP_DS2)
TXP_DS3: C104.2 U12.6(TXP_DS3)
TXP_UP: C1.2 U12.44(TXP_UP)
TXPE_DS2: C98.1 DOWN1.9(TXP)
TXPE_DS3: C104.1 DOWN2.9(TXP)
UART_RX: J1.2 R226.1 U6.24(UART_RX)
UART_TX: J1.1 R68.1 R225.1 U6.23(UART_TX)
USB_DN5V: C118.1 C119.2 C120.1 C121.2 F1.2 F2.2 R176.2 U20.1(VIN) U21.1(VIN)
VDP2: C122.1 C124.2 CE4.1 F1.1 FB2.1 R92.1 R126.1 U20.6(VOUT)
VDP2-1: C96.2 DOWN1.1(VCC) FB2.2
VDP3: C123.1 C125.2 CE5.1 F2.1 FB3.1 R127.1 R138.1 U21.6(VOUT)
VDP3-1: C102.2 DOWN2.1(VCC) FB3.2
WS: U6.43(I2S_WS) U8.3(WS)
X1: C87.1 R123.1 U12.39(X1) Y2.3(OUT)
X2: C88.1 R123.2 U12.38(X2) Y2.1(NC)
XI: C11.2 R24.2 R27.1 U6.17(XIN) Y1.1(NC)
XO: C12.2 R27.2 U6.18(XOUT) Y1.3(OUT)
N19229672: CN1.B5(CC2) R61.1
N19505597: C57.1 LB5.1 U8.9(VA)
N19505631: C60.1 J2.2(R) R76.2
N19505633: C61.1 J2.5(L) R77.2
N19505676: C58.1 U8.10(AOUTR)
N19505678: C58.2 R76.1 R79.1
N19505727: C59.1 U8.7(AOUTL)
N19505729: C59.2 R77.1 R78.1
N19505739: C62.1 U8.5(VQ)
N19505743: C63.1 U8.6(FILT+)
N19596142: R132.2 U12.3(DP3)
N19596147: C77.1 C78.1 C82.2 R158.1 R159.1 U12.25(VDDP) U12.26(V5)
N19596167: R133.2 U12.4(DM3)
N19597124: LED1.K(2) R91.2
N19627230: C34.1 CN3.A5(CC1) ED4.1 R37.2
N19627347: C35.1 CN3.B5(CC2) ED3.1 R39.1
N19627527: C116.1 R44.1 U2.11(ILIM1)
N19627531: C117.1 R45.1 R214.1 U2.1(ILIM2)
N19627614: C36.2 U2.10(SS)
N19627616: C109.2 R215.2 U2.12(VLIM)
N19627618: R50.1 R216.1 U2.9(FLTB)
N19628397: C65.1 L4.1 R86.1 R183.2 U17.1(VIN)
N19628403: L4.2 U17.6(SW) U17.7(SW)
N19628495: C105.2 R83.1 R84.2 U17.4(FB)
N19628610: C44.1 U4.2(VCC)
N19628632: C43.2 L2.1 U4.4(SW)
N19628690: C112.1 R54.1 R56.2 U4.8(EN)
N19628753: C45.2 R55.1 R57.2 U4.1(FB)
N19628785: C48.1 U4.7(SS)
N19699549: L1.1 U15.3(SW)
N19699577: C64.1 R82.2 R163.2 U15.1(EN)
N19699587: C37.2 R52.2 R53.1 U15.5(FB)
N19699777: L3.1 U16.3(SW)
N19699805: R80.2 R81.2 U16.1(EN)
N19699811: C49.2 R58.2 R59.1 U16.5(FB)
N19728059: TP12.1(TP) U6.19(NC)
N19760619: D5.A(ANODE) R48.2
N19769054: C111.2 R178.1
N19810131: C113.1 R183.1 R184.1 U17.2(EN)
N19910853: R204.2 U20.5(ILIM)
N19915017: R207.2 U21.5(ILIM)
N19942881: Q9.D(DRAIN) R210.1
N19946087: R46.1 R213.1 U2.5(EN2)
N19999027: R223.1 U12.41(DP0)
N19999030: R222.1 U12.42(DM0)
N20012349: CN2.14(Utility) R225.2
N20012352: CN2.13(CE_Remote) R226.2

Not connected (* = marked no-connect by the designer): CN3 A2(TX1P)* A3(TX1N)* A6(DP1)* A7(DN1)* A8(SBU1)* A10(RX2N)* A11(RX2P)* B2(TX2P)* B3(TX2N)* B6(DP2)* B7(DN2)* B8(SBU2)* B10(RX1N)* B11(RX1P)*; J2 3(NCR)* 4(NCL)*

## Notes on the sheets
sheet 1
- AG9311-MAQ_QFN64_CtoHDMI_PD_U3HUB
- DATE
- Version
- Update Content
- Page
- Author
- P01: Revision History
  P02: DP to HDMI
  P03: Type-C & Power
  P04: USB3.0 HUB
- 2019.09.18
- 1.0
- Preliminary
- na
- Nash Lee
sheet 2
- Type-C PD Daul Role
- USB3.0
- DP-Alt
- Reserved for-
  -the direct connect device.
- Reserved
- HDMI TX
- low side
- low side
- A level shift reserved.
- Voltage Sense
- TVS close to connecter.
- Choke close to AG9311.
- TVS close to HDMI connecter.
- A01: R24=51K,R27=200K.
  C03: R24=NC, R27=1M.
- Please close to AG9311
- Audio
- Debug Port
- Close to AG9311
- TX
  RX
  GND
- Reserved
- Do Not Recommend using UART for GPIO purpose.
- Close to AG9311
sheet 3
- Power Adaptor Input
- SINK-VIN:
  Sink for Type-C charger Input
- DRP-VBUS:
  Type-C Dual Role
- Power Control
- ILIM=3.5A
- SS=16ms
- OVP=22V
- HV-->5V
  BUCK
- LV-->5V
  BOOST
- R55=118K; Vout=5.1V
  R55=91K: Vout=4.1V
- Vout=5.15V
- MT5035, Iout(max)=3A
- BUCK ONLY: R120=0R, R99=NC, R86=NC
  BOOST: R120=NC, R99=0R, R86=0R
- 5-->3.3V
- 5-->1.2V
- DVDD12=1.23V
sheet 4
- Connect V5(Pin26) to V33
  while using external 3.3V power input
- C79 close to pin29,
  C80 close to pin1
- Individual Mode
- Reserved
- Reserved
- Ilim=1.4A
- 09/27.
